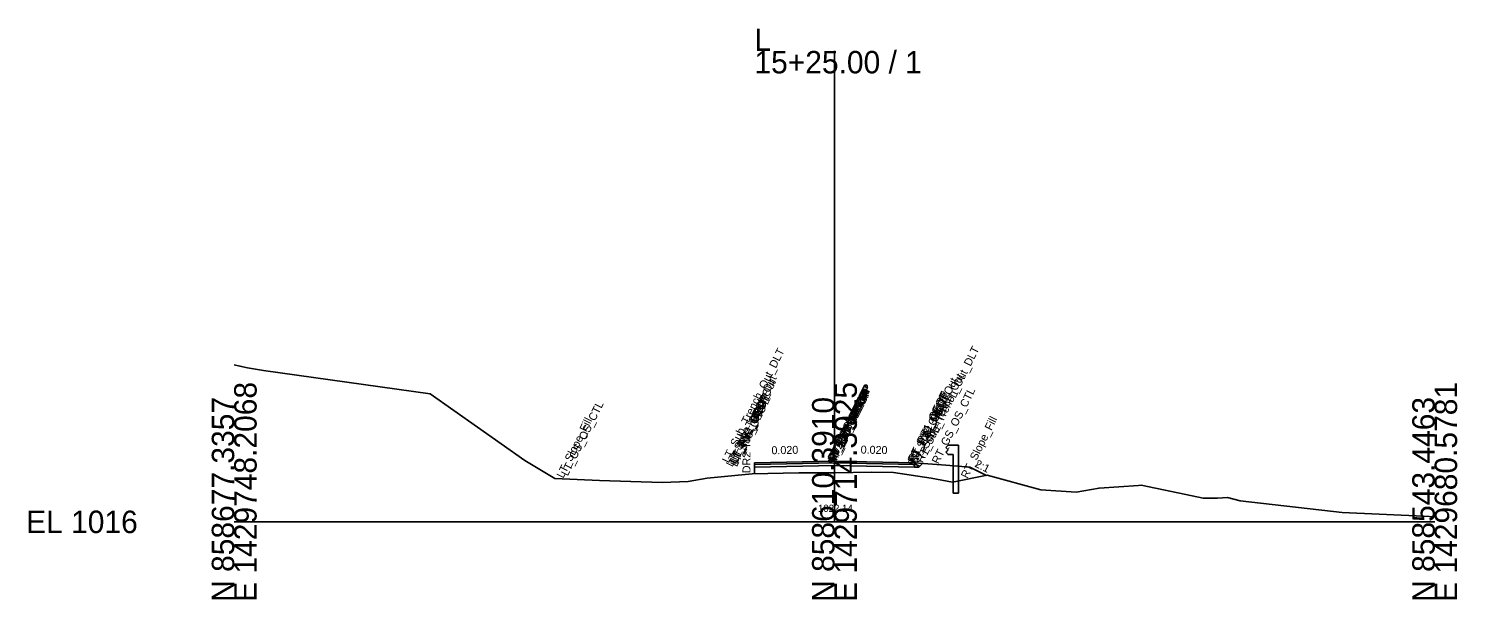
# Model space of a CAD drawing. Extents: x -26 to 153, y -10 to 13058.
# Drawn here: x -25.7 to 152.8, y 7490.3 to 7561.6 of the extents above; entities that cross this region are included whole.
import ezdxf

# ---------------------------------------------------------------- set-up
doc = ezdxf.new("R2010")
doc.units = 0
for name, color, linetype in [('Default', 7, 'Continuous'), ('Exist Cross Section Cell', 7, 'Continuous'), ('Exist XS Ground Line', 7, 'Continuous'), ('Prop CMT Guardrail Graphics', 7, 'Continuous'), ('Prop CMT Pvmt Course 1', 7, 'Continuous'), ('Prop CMT Pvmt Course 2', 7, 'Continuous'), ('Prop CMT Pvmt Surface', 7, 'Continuous'), ('Prop CMT Pvmt Surface Shoulder', 7, 'Continuous'), ('Prop CMT Shld Paved Course 1', 7, 'Continuous'), ('Prop CMT Shld Paved Course 2', 7, 'Continuous'), ('Prop CMT Slope Grass', 7, 'Continuous'), ('Prop CMT Subgrade Daylight Point', 7, 'Continuous'), ('Prop CMT Subgrade Earthwork', 7, 'Continuous'), ('Prop CMT Template Flag', 7, 'Continuous'), ('Prop XS Dump Level', 7, 'Continuous'), ('Prop XS SE Text', 7, 'Continuous'), ('Prop XS Side Slope Text', 7, 'Continuous'), ('Prop XSC Text', 7, 'Continuous')]:
    doc.layers.add(name, color=color, linetype=linetype)

msp = doc.modelspace()

# ---------------------------------------------------------------- linework, layer by layer
at = {"layer": 'Exist Cross Section Cell'}
for p, q in [((75, 7500), (75, 7558.84)), ((0, 7500), (75, 7500)), ((75, 7500), (150, 7500))]:
    msp.add_line(p, q, dxfattribs=at)
at = {"layer": 'Exist XS Ground Line'}
msp.add_lwpolyline([(0, 7519.61), (0.71, 7519.47), (1.67, 7519.25), (3.65, 7518.93), (24.5, 7515.98), (36.31, 7507.68), (40.06, 7505.43), (45.63, 7505.15), (53.46, 7504.93), (56.72, 7505.03), (59.11, 7505.44), (64.72, 7506.01), (70.54, 7506.11), (73.64, 7506.13), (75, 7506.14), (79.63, 7506.19), (82.39, 7506.18), (87.07, 7505.47), (89.77, 7504.96), (94.08, 7505.83), (100.77, 7504.01), (105.19, 7503.69), (108.07, 7504.22), (113.01, 7504.56), (113.32, 7504.57), (119.69, 7503.26), (121.09, 7502.96), (122.86, 7502.97), (124.11, 7503.04), (125.68, 7502.64), (138.45, 7501.15), (148.62, 7500.7), (150, 7500.61)], dxfattribs=at)
at = {"layer": 'Prop CMT Guardrail Graphics'}
for points in [[(90.52, 7509.58), (89.19, 7509.58), (88.92, 7509.29)], [(88.92, 7509.29), (89.19, 7509)], [(90.52, 7503.58), (90.52, 7509.58)], [(89.19, 7509), (88.92, 7508.7)], [(88.92, 7508.7), (89.19, 7508.41), (89.85, 7508.41)], [(89.85, 7508.41), (89.85, 7503.58)], [(89.85, 7503.58), (90.52, 7503.58)]]:
    msp.add_lwpolyline(points, dxfattribs=at)
at = {"layer": 'Prop CMT Pvmt Course 1'}
for points in [[(75, 7507.59), (65, 7507.39)], [(65, 7507.18), (75, 7507.38)], [(75, 7507.38), (75, 7507.59)], [(75, 7507.59), (85, 7507.39)], [(75, 7507.38), (75, 7507.59)], [(85, 7507.18), (75, 7507.38)], [(85, 7507.39), (85, 7507.18)]]:
    msp.add_lwpolyline(points, dxfattribs=at)
msp.add_lwpolyline([(75, 7507.38), (75, 7507.47), (75, 7507.47), (75, 7507.38)], close=True, dxfattribs=at)
msp.add_lwpolyline([(75, 7507.38), (75, 7507.47), (75, 7507.47), (75, 7507.38)], close=True, dxfattribs=at)
at = {"layer": 'Prop CMT Pvmt Course 2'}
for points in [[(75, 7507.38), (65, 7507.18)], [(75, 7507.05), (75, 7507.38)], [(75, 7507.05), (75, 7507.38)], [(75, 7507.38), (85, 7507.18)], [(65, 7506.85), (75, 7507.05)], [(85, 7506.85), (75, 7507.05)], [(85, 7507.18), (85, 7506.85)]]:
    msp.add_lwpolyline(points, dxfattribs=at)
at = {"layer": 'Prop CMT Pvmt Surface'}
for points in [[(75, 7507.59), (65, 7507.39)], [(75, 7507.59), (85, 7507.39)]]:
    msp.add_lwpolyline(points, dxfattribs=at)
at = {"layer": 'Prop CMT Pvmt Surface Shoulder'}
msp.add_lwpolyline([(85, 7507.39), (85, 7507.39)], dxfattribs=at)
at = {"layer": 'Prop CMT Shld Paved Course 1'}
for points in [[(85, 7507.39), (85, 7507.39)], [(85, 7507.39), (85.21, 7507.18)], [(85, 7507.18), (85, 7507.39)], [(85.21, 7507.18), (85, 7507.18)]]:
    msp.add_lwpolyline(points, dxfattribs=at)
at = {"layer": 'Prop CMT Shld Paved Course 2'}
for points in [[(85, 7507.18), (85.21, 7507.18)], [(85, 7506.85), (85, 7507.18)], [(85.55, 7506.84), (85, 7506.85)], [(85.21, 7507.18), (85.21, 7507.18)], [(85.21, 7507.18), (85.55, 7506.84)]]:
    msp.add_lwpolyline(points, dxfattribs=at)
at = {"layer": 'Prop CMT Slope Grass'}
for points in [[(85, 7507.39), (88.92, 7507.08)], [(88.92, 7507.08), (91.92, 7506.84)], [(91.92, 7506.84), (93.98, 7505.81)]]:
    msp.add_lwpolyline(points, dxfattribs=at)
at = {"layer": 'Prop CMT Subgrade Earthwork'}
for points in [[(85.55, 7506.84), (86.02, 7507.31)], [(75, 7507.05), (65, 7506.85)], [(75, 7507.05), (85, 7506.85)], [(85, 7506.85), (85.55, 7506.84)]]:
    msp.add_lwpolyline(points, dxfattribs=at)
at = {"layer": 'Prop CMT Template Flag'}
msp.add_line((65, 7507.39), (65, 7506.02), dxfattribs=at)

# ---------------------------------------------------------------- texts
at = {"layer": 'Default'}
msp.add_text('-', height=0.0001, dxfattribs=at).set_placement((0, 7500))
at = {"layer": 'Exist Cross Section Cell'}
for s, p in [('L', (65, 7558.84)), ('15+25.00 / 1', (65, 7556.04)), ('EL 1016', (-26, 7498.6))]:
    msp.add_text(s, height=2.8, dxfattribs=at).set_placement(p)
for s, p in [('E 1429748.2068', (2.8, 7490)), ('E 1429714.3925', (77.8, 7490)), ('E 1429680.5781', (152.8, 7490)), ('N 858677.3357', (0, 7490)), ('N 858610.3910', (75, 7490)), ('N 858543.4463', (150, 7490))]:
    msp.add_text(s, height=2.8, rotation=90, dxfattribs=at).set_placement(p)
at = {"layer": 'Prop CMT Subgrade Daylight Point'}
msp.add_text('1022.14', height=0.9, dxfattribs=at).set_placement((72.94, 7501.24))
at = {"layer": 'Prop XS Dump Level'}
for s, p in [('LT_Sub_Trench_Out_DLT', (61.79, 7507.27)), ('RT_Sub_Trench_Out_DLT', (86.02, 7507.31)), ('LT_Sub_Trench_Out', (62.26, 7506.8)), ('RT_PS2_Shelf_Out', (85.21, 7507.18)), ('RT_Sub_Trench_Out', (85.55, 7506.84)), ('LT_PS2_Shelf_Out', (62.6, 7507.14)), ('RT_PV1_OEEOP', (75, 7507.47)), ('RT_PV2_OEEOP', (75, 7507.38)), ('LT_PV1_OEEOP', (75, 7507.47)), ('LT_PV2_OEEOP', (75, 7507.38)), ('RT_Sub_OEEOP', (75, 7507.05)), ('RT_PV1_IEEOP', (75, 7507.47)), ('RT_PV2_IEEOP', (75, 7507.38)), ('LT_Sub_OEEOP', (75, 7507.05)), ('LT_PV1_IEEOP', (75, 7507.47)), ('LT_PV2_IEEOP', (75, 7507.38)), ('RT_PV1_OEOT', (85, 7507.39)), ('RT_PS1_OEOP', (85, 7507.39)), ('RT_GS_OS_CTL', (88, 7507.15)), ('LT_GS_OS_CTL', (41.67, 7505.66)), ('LT_PS2_OEOP', (62.6, 7507.14)), ('LT_PV1_OEOT', (62.81, 7507.35)), ('LT_PS1_OEOP', (62.81, 7507.35)), ('LT_PV2_OEOT', (62.81, 7507.14)), ('LT_Sub_OEOT', (62.81, 7506.81)), ('RT_PV2_OEOT', (85, 7507.18)), ('RT_Sub_OEOT', (85, 7506.85)), ('RT_PS2_OEOP', (85.21, 7507.18)), ('LT_Slope_Fill', (41.11, 7505.38)), ('PV1_PGL', (75, 7507.59)), ('PV2_PGL', (75, 7507.38)), ('RT_Slope_Fill', (91.63, 7505.34))]:
    msp.add_text(s, height=1, rotation=63.5833, dxfattribs=at).set_placement(p)
at = {"layer": 'Prop XS SE Text'}
for rotation, p in [(1.1458, (67.14, 7508.44)), (358.8542, (78.27, 7508.53))]:
    msp.add_text('0.020', height=1, rotation=rotation, dxfattribs=at).set_placement(p)
at = {"layer": 'Prop XS Side Slope Text'}
msp.add_text('2:1', height=1, rotation=333.4349, dxfattribs=at).set_placement((92.44, 7506.93))
at = {"layer": 'Prop XSC Text'}
msp.add_text('DR2 TIE', height=1, rotation=90, dxfattribs=at).set_placement((64.51, 7506.08))

doc.saveas('drawing.dxf')
